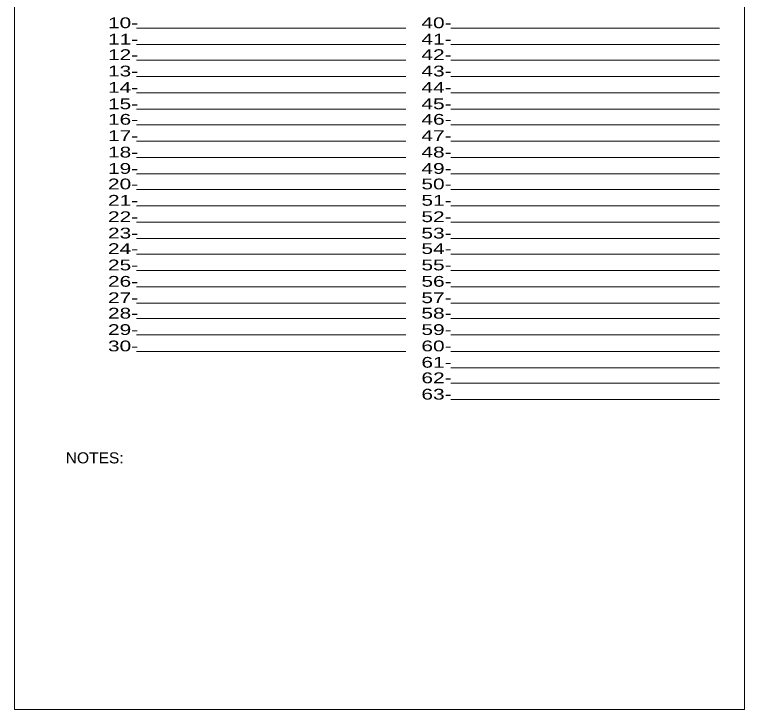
# Model space of a CAD drawing. Extents: x 55 to 190, y 198 to 264.
# Drawn here: x 168.12 to 189.71, y 201.22 to 221.76 of the extents above; entities that cross this region are included whole.
import ezdxf

# ---------------------------------------------------------------- set-up
doc = ezdxf.new("R2010")
doc.units = 0
doc.header["$LTSCALE"] = 0.1
doc.layers.add('3', color=7, linetype='Continuous', lineweight=25)
doc.layers.add('8', color=7, linetype='Continuous', lineweight=13)

msp = doc.modelspace()

# ---------------------------------------------------------------- linework, layer by layer
at = {"layer": '3', "lineweight": 13}
msp.add_lwpolyline([(168.1177, 229.1625), (189.7077, 229.1625), (189.7077, 201.2225), (168.1177, 201.2225)], close=True, dxfattribs=at)
at = {"layer": '8'}
for p, q in [((171.7202, 221.3612), (179.694, 221.3612)), ((181.019, 221.3612), (188.9677, 221.3612)), ((171.7202, 220.8775), (179.694, 220.8775)), ((181.019, 220.8775), (188.9677, 220.8775)), ((171.7202, 220.4187), (179.694, 220.4187)), ((181.019, 220.4187), (188.9677, 220.4187)), ((171.7202, 219.935), (179.694, 219.935)), ((181.019, 219.935), (188.9677, 219.935)), ((171.7202, 219.45), (179.694, 219.45)), ((181.019, 219.45), (188.9677, 219.45)), ((171.7202, 218.9662), (179.694, 218.9662)), ((181.019, 218.9662), (188.9677, 218.9662)), ((171.7202, 218.5075), (179.694, 218.5075)), ((181.019, 218.5075), (188.9677, 218.5075)), ((171.7202, 218.0237), (179.694, 218.0237)), ((181.019, 218.0237), (188.9677, 218.0237)), ((171.7202, 217.5387), (179.694, 217.5387)), ((181.019, 217.5387), (188.9677, 217.5387)), ((171.7202, 217.055), (179.694, 217.055)), ((181.019, 217.055), (188.9677, 217.055)), ((171.7202, 216.5962), (179.694, 216.5962)), ((181.019, 216.5962), (188.9677, 216.5962)), ((171.7202, 216.1125), (179.694, 216.1125)), ((181.019, 216.1125), (188.9677, 216.1125)), ((171.7202, 215.6287), (179.694, 215.6287)), ((181.019, 215.6287), (188.9677, 215.6287)), ((171.7202, 215.1437), (179.694, 215.1437)), ((181.019, 215.1437), (188.9677, 215.1437)), ((171.7202, 214.685), (179.694, 214.685)), ((181.019, 214.685), (188.9677, 214.685)), ((171.7202, 214.2012), (179.694, 214.2012)), ((181.019, 214.2012), (188.9677, 214.2012)), ((171.7202, 213.7175), (179.694, 213.7175)), ((181.019, 213.7175), (188.9677, 213.7175)), ((171.7202, 213.2325), (179.694, 213.2325)), ((181.019, 213.2325), (188.9677, 213.2325)), ((171.7202, 212.7762), (179.694, 212.7762)), ((181.019, 212.7762), (188.9677, 212.7762)), ((171.7202, 212.2912), (179.694, 212.2912)), ((181.019, 212.2912), (188.9677, 212.2912)), ((171.7202, 211.8075), (179.694, 211.8075)), ((181.019, 211.8075), (188.9677, 211.8075)), ((181.019, 211.3237), (188.9677, 211.3237)), ((181.019, 210.865), (188.9677, 210.865)), ((181.019, 210.3812), (188.9677, 210.3812))]:
    msp.add_line(p, q, dxfattribs=at)

# ---------------------------------------------------------------- texts
for s, height, width, p in [('10-', 0.3184, 1.45, (170.8802, 221.3612)), ('40-', 0.3184, 1.45, (180.1527, 221.3612)), ('11-', 0.3184, 1.45, (170.8802, 220.8775)), ('41-', 0.3184, 1.45, (180.1527, 220.8775)), ('12-', 0.3184, 1.45, (170.8802, 220.4187)), ('42-', 0.3184, 1.45, (180.1527, 220.4187)), ('13-', 0.3184, 1.45, (170.8802, 219.935)), ('43-', 0.3184, 1.45, (180.1527, 219.935)), ('14-', 0.3184, 1.45, (170.8802, 219.45)), ('44-', 0.3184, 1.45, (180.1527, 219.45)), ('15-', 0.3184, 1.45, (170.8802, 218.9662)), ('45-', 0.3184, 1.45, (180.1527, 218.9662)), ('16-', 0.3184, 1.45, (170.8802, 218.5075)), ('46-', 0.3184, 1.45, (180.1527, 218.5075)), ('17-', 0.3184, 1.45, (170.8802, 218.0237)), ('47-', 0.3184, 1.45, (180.1527, 218.0237)), ('18-', 0.3184, 1.45, (170.8802, 217.5387)), ('48-', 0.3184, 1.45, (180.1527, 217.5387)), ('19-', 0.3184, 1.45, (170.8802, 217.055)), ('49-', 0.3184, 1.45, (180.1527, 217.055)), ('20-', 0.3184, 1.45, (170.8802, 216.5962)), ('50-', 0.3184, 1.45, (180.1527, 216.5962)), ('21-', 0.3184, 1.45, (170.8802, 216.1125)), ('51-', 0.3184, 1.45, (180.1527, 216.1125)), ('22-', 0.3184, 1.45, (170.8802, 215.6287)), ('52-', 0.3184, 1.45, (180.1527, 215.6287)), ('23-', 0.3184, 1.45, (170.8802, 215.1437)), ('53-', 0.3184, 1.45, (180.1527, 215.1437)), ('24-', 0.3184, 1.45, (170.8802, 214.685)), ('54-', 0.3184, 1.45, (180.1527, 214.685)), ('25-', 0.3184, 1.45, (170.8802, 214.2012)), ('55-', 0.3184, 1.45, (180.1527, 214.2012)), ('26-', 0.3184, 1.45, (170.8802, 213.7175)), ('56-', 0.3184, 1.45, (180.1527, 213.7175)), ('27-', 0.3184, 1.45, (170.8802, 213.2325)), ('57-', 0.3184, 1.45, (180.1527, 213.2325)), ('28-', 0.3184, 1.45, (170.8802, 212.7762)), ('58-', 0.3184, 1.45, (180.1527, 212.7762)), ('29-', 0.3184, 1.45, (170.8802, 212.2912)), ('59-', 0.3184, 1.45, (180.1527, 212.2912)), ('30-', 0.3184, 1.45, (170.8802, 211.8075)), ('60-', 0.3184, 1.45, (180.1527, 211.8075)), ('61-', 0.3184, 1.45, (180.1527, 211.3237)), ('62-', 0.3184, 1.45, (180.1527, 210.865)), ('63-', 0.3184, 1.45, (180.1527, 210.3812)), ('NOTES:', 0.3275, 1.05, (169.6315, 208.495))]:
    msp.add_text(s, height=height, dxfattribs=dict(at, width=width)).set_placement(p)

doc.saveas('drawing.dxf')
